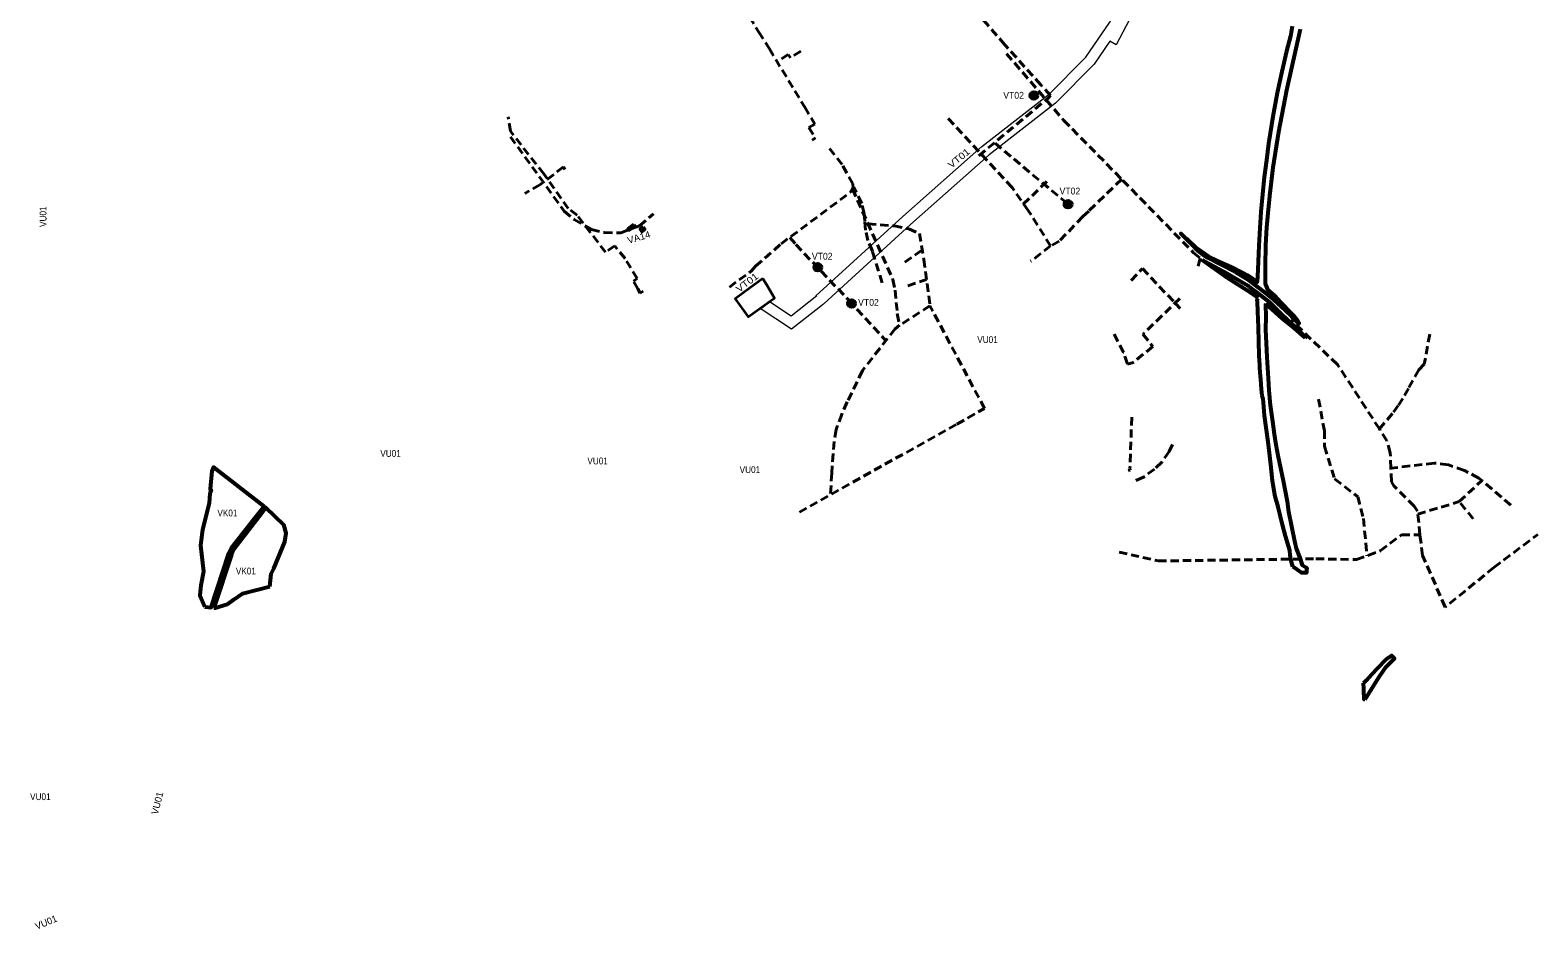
# Model space of a CAD drawing. Extents: x -650145 to -642675, y -1074338 to -1066724.
# Drawn here: x -648976 to -644548, y -1074338 to -1071699 of the extents above; entities that cross this region are included whole.
import ezdxf

# ---------------------------------------------------------------- set-up
doc = ezdxf.new("R2010")
doc.units = 0
doc.header["$LTSCALE"] = 8
doc.linetypes.add('MEDIUM_DASHED', pattern=[4.5, 3, -1.5])
for name, color, linetype in [('1', 7, 'Continuous'), ('17', 7, 'Continuous'), ('2', 7, 'Continuous'), ('3', 7, 'Continuous')]:
    doc.layers.add(name, color=color, linetype=linetype)
for name, color, linetype, lineweight in [('12', 7, 'MEDIUM_DASHED', 40), ('15', 7, 'Continuous', 13), ('45', 7, 'Continuous', 53), ('60', 7, 'Continuous', 53)]:
    doc.layers.add(name, color=color, linetype=linetype, lineweight=lineweight)

msp = doc.modelspace()

# ---------------------------------------------------------------- hatches: boundary and pattern name
at = {"layer": '15'}
for points in [[(-646016.453, -1071890.987, 1), (-646039.978, -1071890.987, 1)], [(-645916.109, -1072210.132, 1), (-645939.634, -1072210.132, 1)], [(-646651.182, -1072395.364, 1), (-646674.706, -1072395.364, 1)], [(-646551.973, -1072501.882, 1), (-646575.498, -1072501.882, 1)]]:
    msp.add_hatch(color=256, dxfattribs=at).paths.add_polyline_path(points)
at = {"layer": '60'}
for points in [[(-647203.48, -1072271.1), (-647219.86, -1072283.16), (-647217.95, -1072285.83), (-647201.52, -1072273.8)], [(-647175.95, -1072277.72), (-647183.77, -1072283.6), (-647179.89, -1072288.9), (-647172.06, -1072283.01)]]:
    msp.add_hatch(color=256, dxfattribs=at).paths.add_polyline_path(points)

# ---------------------------------------------------------------- linework, layer by layer
at = {"layer": '12'}
for p, q in [((-646142.308, -1072031.286), (-645934.368, -1072204.655)), ((-645990.194, -1072143.593), (-646067.454, -1072218.303)), ((-646406.679, -1072380.519), (-646355.921, -1072344.291)), ((-646398.36, -1072449.736), (-646343.369, -1072431.172)), ((-644737.523, -1073134.312), (-644778.948, -1073083.582)), ((-644677.063, -1073276.773), (-644547.878, -1073179.588))]:
    msp.add_line(p, q, dxfattribs=at)
for points in [[(-646901.7, -1071599.29), (-646836.01, -1071704.74), (-646804.94, -1071754.31)], [(-645979.173, -1071891.235), (-646007.318, -1071860.17), (-646113.522, -1071742.176), (-646203.196, -1071638.82), (-646210.712, -1071621.148)], [(-646804.94, -1071754.31), (-646701.24, -1071925.46), (-646671.37, -1071974.86)], [(-646712.71, -1071760.64), (-646743.06, -1071780.15), (-646749.35, -1071770.55), (-646782.673, -1071791.06)], [(-646108.34, -1071768.288), (-645991.774, -1071903.675), (-645940.8, -1071963.54), (-645766.873, -1072140.424), (-645559.153, -1072352.891), (-645539.728, -1072368.513), (-645547.013, -1072398.199)], [(-646190.163, -1072068.09), (-645983.794, -1071896.963), (-645979.173, -1071891.234)], [(-647369.65, -1072242.58), (-647395.603, -1072222.827), (-647467.645, -1072120.835), (-647565.59, -1071996.178), (-647571.937, -1071954.126)], [(-646671.37, -1071974.86), (-646688.66, -1071985.16), (-646669.77, -1072015.67), (-646679.35, -1072021.71)], [(-645978.908, -1072332.844), (-646044.53, -1072228.907), (-646091.859, -1072161.141), (-646284.4, -1071953.541)], [(-647565.274, -1072012.581), (-647407.42, -1072230.889), (-647378.312, -1072255.368), (-647327.486, -1072284.458), (-647289.597, -1072293.583), (-647241.628, -1072293.997), (-647186.201, -1072273.818), (-647145.51, -1072238.04)], [(-646922.495, -1072453.643), (-646857.191, -1072406.111), (-646845.696, -1072392.061), (-646770.684, -1072326.695), (-646564.651, -1072173.134), (-646559.323, -1072162.51), (-646560.242, -1072150.62), (-646591.477, -1072093.57), (-646627.948, -1072046.396)], [(-647405.694, -1072108.1), (-647409.897, -1072100.921), (-647478.896, -1072153.329), (-647523.403, -1072178.874)], [(-645770.117, -1072137.125), (-645867.081, -1072230.375), (-645887.539, -1072249.441)], [(-646560.829, -1072165.418), (-646442.617, -1072430.974), (-646435.336, -1072462.744), (-646429.379, -1072531.58), (-646422.811, -1072565.755), (-646435.637, -1072576.085), (-646531.76, -1072698.93), (-646576.398, -1072790.696), (-646592.362, -1072826.343), (-646608.607, -1072871.571), (-646614.559, -1072906.613), (-646622.02, -1072999.792), (-646625.456, -1073063.469)], [(-646515.621, -1072316.407), (-646522.296, -1072286.272), (-646525.05, -1072259.936), (-646526.73, -1072237.276), (-646533.563, -1072207.871), (-646557.282, -1072161.242)], [(-647191.37, -1072458.86), (-647204.41, -1072436.35), (-647193.17, -1072428.14), (-647228.9, -1072369.98), (-647259.29, -1072332.91), (-647286.03, -1072350.98), (-647368.027, -1072244.683)], [(-646515.068, -1072268.004), (-646438.375, -1072274.017), (-646395.81, -1072282.852), (-646364.347, -1072296.336), (-646351.055, -1072371.983), (-646333.32, -1072508.549)], [(-645884.618, -1072246.363), (-645953.602, -1072319.058), (-645978.908, -1072332.844), (-646038.138, -1072377.943)], [(-646744.92, -1072307.492), (-646727.261, -1072328.683), (-646572.036, -1072491.987), (-646462.937, -1072610.974)], [(-646474.01, -1072441.461), (-646502.208, -1072348.07), (-646515.621, -1072316.407)], [(-645742.473, -1072433.786), (-645709.258, -1072399.404), (-645598.422, -1072516.199)], [(-647175.32, -1072466), (-647184.36, -1072470.98), (-647191.37, -1072458.86)], [(-646716.85, -1073114.625), (-646254.197, -1072855.664), (-646173.155, -1072809.893), (-646333.32, -1072508.549), (-646422.811, -1072565.755)], [(-645599.642, -1072487.459), (-645707.673, -1072591.746), (-645678.856, -1072628.004), (-645736.077, -1072674.835), (-645752.766, -1072679.471), (-645764.412, -1072645.375), (-645793.32, -1072590.47)], [(-644677.063, -1073276.773), (-644820.09, -1073393.239), (-644886.431, -1073241.755), (-644894.218, -1073180.725), (-644901.367, -1073111.484), (-644910.953, -1073097.104), (-644970.414, -1073037.091), (-644977.617, -1073024.956), (-644979.519, -1072985.65), (-644981.225, -1072940.656), (-644991.691, -1072905.052), (-645013.264, -1072869.98), (-645136.284, -1072680.783), (-645273.573, -1072549.71)], [(-644865.163, -1072591.801), (-644881.47, -1072679.739), (-644897.776, -1072696.046), (-644928.014, -1072751.285)], [(-644928.014, -1072751.285), (-644944.228, -1072780.29), (-644958.247, -1072801.452), (-644975.175, -1072824.929), (-645013.264, -1072869.98)], [(-645191.679, -1072782.461), (-645175.001, -1072875.23), (-645175.001, -1072921.093), (-645144.773, -1073016.989), (-645077.02, -1073069.106), (-645059.861, -1073133.007), (-645050.18, -1073242.481)], [(-645740.627, -1072835.69), (-645745.906, -1072985.427), (-645745.265, -1072991.028), (-645750.784, -1072992.05)], [(-645621.405, -1072915.798), (-645630.523, -1072936.275), (-645652.44, -1072967.63), (-645673.716, -1072987.946), (-645706.351, -1073011.942), (-645739.675, -1073026.324)], [(-644627.418, -1073093.922), (-644720.94, -1073014.135), (-644763.53, -1072992.287), (-644810.544, -1072975.14), (-644851.751, -1072970.162), (-644979.519, -1072985.65)], [(-644900.454, -1073120.324), (-644778.948, -1073083.582), (-644712.07, -1073021.703)], [(-645777.988, -1073231.981), (-645662.45, -1073257.758), (-645199.545, -1073251.421), (-645080.605, -1073253.501), (-645010.848, -1073228.236), (-644948.284, -1073180.725), (-644894.218, -1073180.725)]]:
    msp.add_lwpolyline(points, dxfattribs=at)
at = {"layer": '15', "lineweight": 35}
msp.add_line((-646832.318, -1072516.145), (-646804.328, -1072496.262), dxfattribs=at)
at = {"layer": '15'}
for points in [[(-645985.984, -1071889.912), (-645875.751, -1071778.476), (-645805.025, -1071675.361), (-645627.872, -1071341.184), (-645225.385, -1071341.796), (-645184.278, -1071232.417)], [(-645184.278, -1071232.417), (-645183.56, -1071242.5), (-645178.87, -1071266.352), (-645207.234, -1071341.824), (-645170.274, -1071341.88), (-645167.04, -1071373.884), (-645592.784, -1071373.238), (-645786.781, -1071742.105), (-645804.579, -1071731.285)], [(-645804.579, -1071731.285), (-645850.985, -1071798.942), (-645964.716, -1071913.914)], [(-646668.175, -1072479.188), (-646413.327, -1072245.835), (-646181.43, -1072040.387), (-645987.337, -1071889.954)], [(-645964.715, -1071913.913), (-646159.64, -1072064.991), (-646390.555, -1072269.569), (-646645.209, -1072502.744)], [(-646646.125, -1072503.522), (-646739.733, -1072577.115), (-646832.318, -1072516.145), (-646804.328, -1072496.262)], [(-646804.328, -1072496.262), (-646741.387, -1072537.711), (-646665.903, -1072478.366)]]:
    msp.add_lwpolyline(points, dxfattribs=at)
at = {"layer": '15', "lineweight": 35}
msp.add_lwpolyline([(-646824.42, -1072428.58), (-646878.91, -1072468.54), (-646905.18, -1072487.8), (-646867.283, -1072540.984), (-646791.569, -1072487.198), (-646790.354, -1072486.136), (-646810.77, -1072451.09)], close=True, dxfattribs=at)
for centre in [(-646028.216, -1071890.987), (-645927.872, -1072210.132), (-646662.944, -1072395.364), (-646563.736, -1072501.882)]:
    msp.add_circle(centre, 11.762, dxfattribs=at)
at = {"layer": '45'}
msp.add_line((-645267.525, -1073275.443), (-645271.518, -1073261.16), dxfattribs=at)
for points in [[(-645269.077, -1071687.396), (-645274.868, -1071717.176), (-645286.175, -1071761.228), (-645300.076, -1071820.179), (-645313.153, -1071883.081), (-645326.343, -1071952.807), (-645334.118, -1072001.954), (-645339.455, -1072031.565), (-645344.819, -1072081.225), (-645351.358, -1072130.815), (-645361.317, -1072232.824), (-645364.435, -1072280.268), (-645366.951, -1072331.609), (-645370.624, -1072401.447), (-645372.228, -1072438.764), (-645387.894, -1072427.453), (-645401.441, -1072419.033), (-645414.631, -1072411.611), (-645448.831, -1072394.325), (-645488.64, -1072376.782), (-645515.437, -1072363.447), (-645547.593, -1072340.827), (-645577.33, -1072312.704), (-645579.217, -1072312.425), (-645596.405, -1072296.114), (-645564.4, -1072328.61), (-645547.72, -1072346.19), (-645532.07, -1072358.01), (-645531.65, -1072358.29), (-645528.27, -1072360.53), (-645519.57, -1072366.3), (-645438.64, -1072408.1), (-645437.6, -1072408.64), (-645434.19, -1072410.67), (-645399.77, -1072431.12), (-645371.356, -1072453.119), (-645342.284, -1072475.625), (-645333.62, -1072482.33), (-645290.76, -1072520.92), (-645271.74, -1072539.96), (-645249.9, -1072561.25), (-645248.967, -1072559.511), (-645252.768, -1072552.178), (-645265.009, -1072538.358), (-645272.276, -1072530.154), (-645302.303, -1072499.014), (-645320.805, -1072479.495), (-645339.904, -1072462.677), (-645347.551, -1072443.527), (-645347.677, -1072391.355), (-645346.62, -1072330.914), (-645343.458, -1072278.998), (-645339.908, -1072235.158), (-645335.367, -1072185.207), (-645325.498, -1072102.789), (-645309.01, -1071998.147), (-645285.617, -1071875.733), (-645244.798, -1071696.585)], [(-645462.646, -1072425.015), (-645534.301, -1072374.332), (-645533.08, -1072373.71)], [(-645533.08, -1072373.71), (-645527.33, -1072377.73), (-645459.31, -1072413.95), (-645456.52, -1072415.6), (-645400.12, -1072449.03), (-645396.94, -1072451.44), (-645370.226, -1072471.736)], [(-645369.364, -1072485.931), (-645389.731, -1072471.612), (-645462.646, -1072425.015)], [(-645364.524, -1072682.575), (-645366.022, -1072654.462), (-645368.173, -1072571.881), (-645370.755, -1072525.734), (-645370.928, -1072496.619), (-645372.72, -1072490.314), (-645369.364, -1072485.931)], [(-645370.226, -1072471.736), (-645362.81, -1072477.37), (-645345.079, -1072490.836)], [(-645347.292, -1072502.877), (-645348.253, -1072505.583), (-645347.214, -1072540.97), (-645347.795, -1072577.893), (-645344.152, -1072658.857), (-645339.96, -1072721.587), (-645338.023, -1072755.969), (-645333.718, -1072799.987)], [(-645230.845, -1072602.888), (-645263.217, -1072574.314), (-645298.498, -1072545.352), (-645347.292, -1072502.877)], [(-645345.079, -1072490.836), (-645336.33, -1072497.48), (-645306.46, -1072527.08), (-645276.93, -1072555.11), (-645263.7, -1072567.8), (-645242, -1072588.6), (-645241.87, -1072588.722), (-645228.96, -1072600.865), (-645230.845, -1072602.888)], [(-645357.272, -1072772.771), (-645359.76, -1072752.865), (-645361.874, -1072723.527), (-645362.708, -1072714.781), (-645364.786, -1072692.977), (-645364.524, -1072682.575)], [(-645271.518, -1073261.16), (-645272.747, -1073256.762), (-645275.269, -1073240.71), (-645276.125, -1073226.571), (-645288.647, -1073184.518), (-645297.395, -1073151.294), (-645310.558, -1073098.946), (-645319.052, -1073068.6), (-645327.554, -1073022.214), (-645332.517, -1072974.538), (-645337.34, -1072932.073), (-645340.345, -1072908.029), (-645350.822, -1072830.388), (-645354.019, -1072792.454), (-645355.121, -1072782.993), (-645357.272, -1072772.771)], [(-645333.718, -1072799.987), (-645327.091, -1072848.387), (-645322.284, -1072885.085), (-645317.65, -1072916.642)], [(-645317.65, -1072916.642), (-645311.772, -1072947.945), (-645304.24, -1072985.372), (-645295.788, -1073022.556)], [(-648463.25, -1073392.125), (-648444.523, -1073394.235), (-648392.43, -1073235.98), (-648384.6, -1073219.54), (-648315.955, -1073131.889), (-648289.148, -1073097.66), (-648437.643, -1072982.601), (-648442.187, -1072994.5), (-648447.043, -1073046.967), (-648444.11, -1073048.69), (-648448.1, -1073058.393)], [(-645295.788, -1073022.556), (-645284.269, -1073083.286), (-645279.878, -1073113.356), (-645262.388, -1073199.409), (-645257.842, -1073221.36), (-645247.051, -1073248.736), (-645239.9, -1073270.025), (-645226.847, -1073278.345), (-645227.199, -1073283.366), (-645227.744, -1073292.736), (-645241.72, -1073292.2), (-645263.03, -1073278.25), (-645267.525, -1073275.443)], [(-648448.1, -1073058.393), (-648450.875, -1073088.375), (-648469.875, -1073165.5), (-648475.437, -1073212.375), (-648466.687, -1073288.25), (-648474.5, -1073328.75), (-648477.562, -1073358.875), (-648463.25, -1073392.125)], [(-648272.642, -1073332.558), (-648268, -1073296), (-648261, -1073280), (-648228, -1073202), (-648224, -1073176), (-648231, -1073152), (-648283.884, -1073101.15), (-648311.798, -1073137.127), (-648378.17, -1073222.67), (-648385.09, -1073238.58), (-648436.857, -1073395.099)], [(-648397.062, -1073384.375), (-648378.125, -1073370.875), (-648352.312, -1073353), (-648314.687, -1073343.25), (-648272.642, -1073332.558)], [(-648436.857, -1073395.099), (-648432.187, -1073395.625), (-648397.062, -1073384.375)], [(-645060.009, -1073616.53), (-645051.513, -1073608.124), (-645035.303, -1073590.199), (-645020.11, -1073573.585), (-644993.044, -1073546.324), (-644977.924, -1073535.072), (-644969.117, -1073544.254), (-644985.66, -1073560.69), (-644996.41, -1073571.97), (-645001.267, -1073578.582), (-645015.55, -1073599.96), (-645043.35, -1073644.04), (-645056.06, -1073664.2)], [(-645056.06, -1073664.2), (-645057.87, -1073664.55), (-645058.01, -1073661.37), (-645058.42, -1073652.18), (-645058.65, -1073647), (-645058.96, -1073640.09), (-645059.35, -1073631.3), (-645060.009, -1073616.53)]]:
    msp.add_lwpolyline(points, dxfattribs=at)
at = {"layer": '60'}
for points in [[(-647203.48, -1072271.1), (-647219.86, -1072283.16), (-647217.95, -1072285.83), (-647201.52, -1072273.8)], [(-647175.95, -1072277.72), (-647183.77, -1072283.6), (-647179.89, -1072288.9), (-647172.06, -1072283.01)]]:
    msp.add_lwpolyline(points, close=True, dxfattribs=at)

# ---------------------------------------------------------------- texts
at = {"layer": '1', "width": 0.9}
for p in [(-648426.286, -1073126.802), (-648372.004, -1073297.285)]:
    msp.add_text('VK01', height=20, dxfattribs=at).set_placement(p)
at = {"layer": '17', "width": 0.95}
for p in [(-646118.047, -1071900.373), (-645952.7, -1072181.661), (-646680.229, -1072372.978), (-646544.334, -1072508.451)]:
    msp.add_text('VT02', height=20, dxfattribs=at).set_placement(p)
at = {"layer": '17', "width": 1.15}
for rotation, p in [(39.483, (-646270.392, -1072106.216)), (37.163, (-646893.836, -1072470.401))]:
    msp.add_text('VT01', height=20, rotation=rotation, dxfattribs=at).set_placement(p)
at = {"layer": '2', "width": 0.9}
msp.add_text('VU01', height=20, rotation=90, dxfattribs=at).set_placement((-648928.323, -1072276.985))
for p in [(-646194.406, -1072617.656), (-647947.746, -1072951.906), (-647339.543, -1072974.017), (-646892.266, -1072999.605), (-648976.371, -1073959.861)]:
    msp.add_text('VU01', height=20, dxfattribs=at).set_placement(p)
at = {"layer": '2'}
for rotation, p in [(75.792, (-648601.32, -1074003.735)), (22.398, (-648956.62, -1074340.801))]:
    msp.add_text('VU01', height=20, rotation=rotation, dxfattribs=at).set_placement(p)
at = {"layer": '3', "width": 1.05}
msp.add_text('VA14', height=20, rotation=16.632, dxfattribs=at).set_placement((-647218.51, -1072326.887))

doc.saveas('drawing.dxf')
